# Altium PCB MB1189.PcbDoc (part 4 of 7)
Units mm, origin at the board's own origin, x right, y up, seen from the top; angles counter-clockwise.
Board outline 60.03 x 127.03 mm, 6 copper layers (TOP, L2_GND, L3_VCC, L4_SIG, L5_GND, BOTTOM), stack 1.58 mm thick; 273 components, 264 nets, 1114 pads, 811 vias.
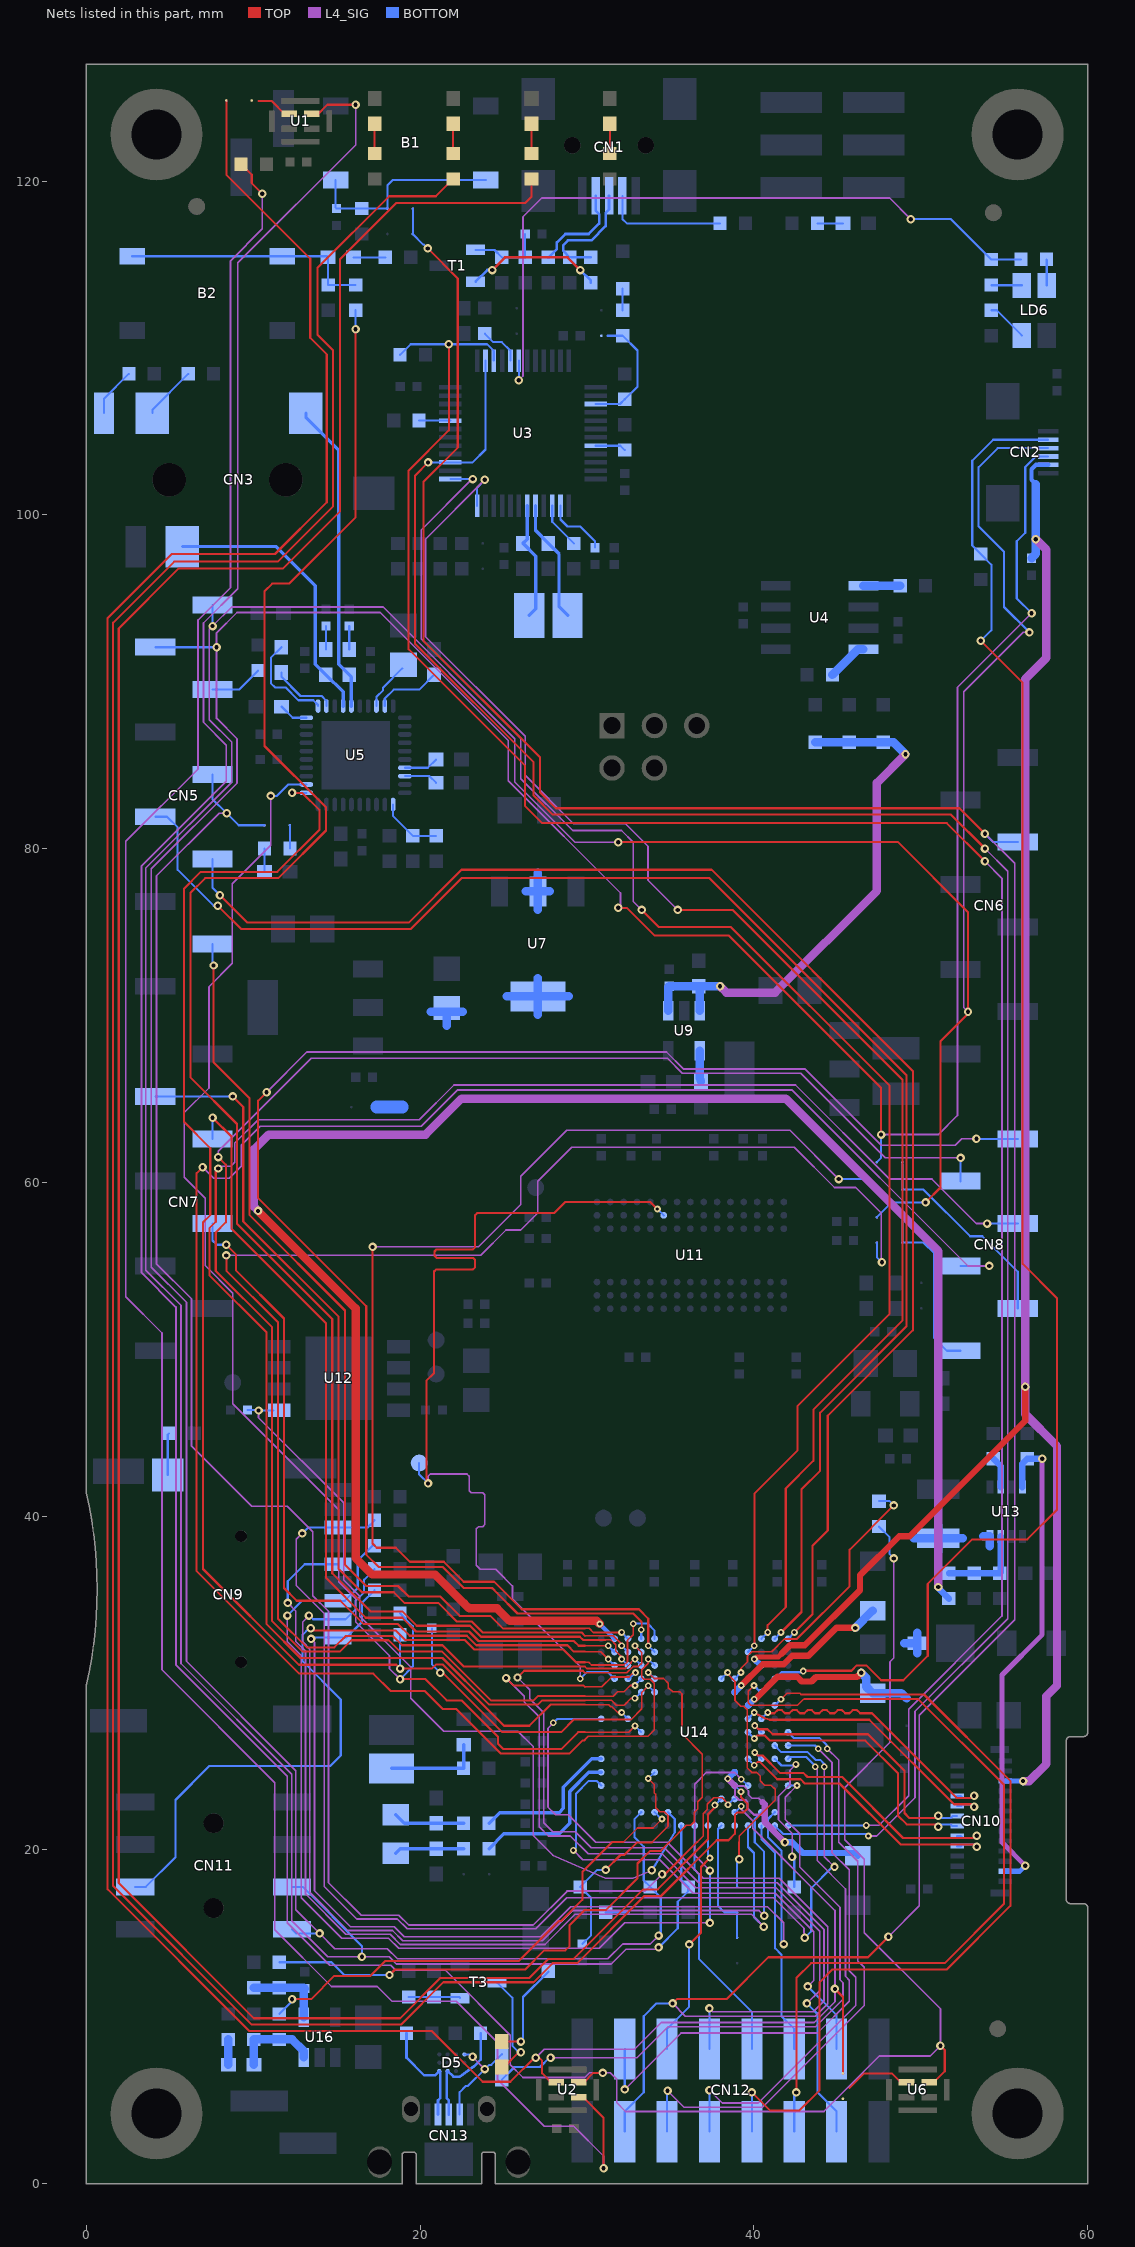
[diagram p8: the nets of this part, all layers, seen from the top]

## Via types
v1: diameter 0.61/0.61/0.61 (per signal layer), hole 0.305, TOP to BOTTOM, 321 vias
v2: diameter 0.508/0.508/0.508 (per signal layer), hole 0.254, TOP to BOTTOM, 247 vias
v3: diameter 0.406/0.406/0.406 (per signal layer), hole 0.203, TOP to BOTTOM, 243 vias

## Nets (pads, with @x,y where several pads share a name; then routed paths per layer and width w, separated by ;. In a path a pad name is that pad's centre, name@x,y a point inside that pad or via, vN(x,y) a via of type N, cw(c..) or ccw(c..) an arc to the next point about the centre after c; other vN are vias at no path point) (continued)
HSSI_CLK_N: CN10.12 U14.H13 | length 16.6
  TOP w0.129: v3(40.056,27.444) 40.271,27.229 40.818,27.229 41.123,26.924 46.838,26.924 49.022,24.74 49.022,22.205 49.32,21.907 50.913,21.907 v2(51.052,22.047)
  BOTTOM w0.13: v3(40.056,27.444) U14.H13@40.449,27.051 ; v2(51.052,22.047) 51.192,21.907 51.794,21.907 51.903,22.017 CN10.12@52.175,22.017
HSSI_CLK_P: CN10.14 U14.H12 | length 16.6
  TOP w0.129: v3(40.03,26.67) 40.208,26.848 40.66,26.848 40.965,26.543 46.68,26.543 48.641,24.582 48.641,22.047 49.162,21.526 50.913,21.526 v2(51.052,21.387)
  BOTTOM w0.13: U14.H12@39.649,27.051 v3(40.03,26.67) ; v2(51.052,21.387) 51.192,21.526 51.794,21.526 51.903,21.417 CN10.14@52.175,21.417
HSSI_D0_N: CN10.8 U14.J13 | length 17.2
  TOP w0.129: v3(40.826,28.228) 40.874,28.18 41.221,28.18 41.413,28.372 41.672,28.372 41.863,28.18 42.122,28.18 42.314,28.372 42.573,28.372 42.764,28.18 43.024,28.18 43.215,28.372 43.474,28.372 43.666,28.18 43.925,28.18 44.116,28.372 44.375,28.372 44.567,28.18 44.826,28.18 45.017,28.372 45.277,28.372 45.468,28.18 45.727,28.18 45.919,28.372 46.178,28.372 46.369,28.18 47.08,28.18 52.153,23.107 53.057,23.107 v2(53.197,23.247)
  BOTTOM w0.13: U14.J13@40.449,27.851 v3(40.826,28.228) ; CN10.8@52.175,23.217 52.411,23.217 52.521,23.107 53.057,23.107 v2(53.197,23.247)
HSSI_D0_P: CN10.10 U14.J12 | length 17.1
  TOP w0.129: v3(40.026,28.228) 40.238,28.096 40.686,27.865 40.945,27.799 46.922,27.799 51.995,22.726 53.057,22.726 v2(53.197,22.586)
  BOTTOM w0.13: U14.J12@39.649,27.851 v3(40.026,28.228) ; CN10.10@52.175,22.617 52.411,22.617 52.521,22.726 53.057,22.726 v2(53.197,22.586)
HSSI_D1_N: CN10.16 U14.F13 | length 17.3
  TOP w0.129: v3(40.056,25.832) 40.234,25.654 40.513,25.654 41.554,24.613 42.957,24.613 43.211,24.359 45.288,24.359 48.94,20.707 53.209,20.707 v2(53.349,20.847)
  BOTTOM w0.13: v3(40.056,25.832) 40.068,25.832 U14.F13@40.449,25.451 ; CN10.16@52.175,20.817 52.411,20.817 52.521,20.707 53.209,20.707 v2(53.349,20.847)
HSSI_D1_P: CN10.18 U14.F12 | length 17.3
  TOP w0.129: v3(40.026,25.074) 40.225,25.273 40.355,25.273 41.396,24.232 42.799,24.232 43.053,23.978 45.13,23.978 48.782,20.326 53.209,20.326 v2(53.349,20.186)
  BOTTOM w0.13: U14.F12@39.649,25.451 v3(40.026,25.074) ; CN10.18@52.175,20.217 52.411,20.217 52.521,20.326 53.209,20.326 v2(53.349,20.186)
I2C1_SCL: CN2.3 CN5.10 CN11.3 R140.2 SB11.1 U14.A7 | length 240.3
  TOP w0.127: v2(31.877,80.391) 48.641,80.391 52.832,76.2 v2(52.832,70.231) 52.832,70.104 51.181,68.453 51.181,59.69 v2(50.292,58.801)
  L4_SIG w0.102: v2(31.877,80.391) 29.279,80.391 25.669,84.001 25.669,86.599 17.78,94.488 8.7,94.488 v2(7.556,93.345) 7.366,93.154 7.366,87.732 8.7,86.398 8.7,83.985 3.556,78.842 3.556,54.737 5.664,52.629 5.664,31.166 12.294,24.536 12.294,15.748 14.453,13.589 v2(16.51,13.589) 18.136,13.589 18.567,13.157 31.445,13.157 32.334,14.046 34.188,14.046 v2(34.29,14.148) ; v2(52.832,70.231) 52.578,70.485 52.578,89.408 56.134,92.964 v2(56.515,92.964)
  BOTTOM w0.127: v2(7.556,93.345) CN5.10@7.556,94.615 ; CN11.3@12.318,17.78 12.954,17.78 16.51,14.224 v2(16.51,13.589) ; v2(34.29,14.148) 35.433,15.291 35.433,16.891 36.068,17.526 R140.2@36.068,17.78 35.649,18.199 U14.A7@35.649,21.451 ; SB11.1@47.371,57.912 48.26,58.801 v2(50.292,58.801) ; v2(56.515,92.964) 54.991,94.488 54.991,97.79 53.467,99.314 53.467,102.87 54.606,104.009 CN2.3@57.635,104.009
I2C1_SDA: CN2.4 CN5.9 CN11.1 R142.2 SB9.1 U14.B4 | length 226.7
  TOP w0.127: v2(31.877,76.454) 32.385,76.454 34.036,74.803 38.481,74.803 47.625,65.659 v2(47.625,62.865)
  L4_SIG w0.102: v2(31.877,76.454) 32.004,76.581 32.004,77.343 25.273,84.074 25.273,86.487 17.602,94.158 9.017,94.158 7.798,92.939 v2(7.798,92.075) 7.798,87.808 9.017,86.589 9.017,83.922 3.886,78.791 3.886,54.915 5.994,52.807 5.994,31.293 12.548,24.74 12.548,16.408 v2(13.97,14.986) 14.884,14.072 18.034,14.072 18.644,13.462 31.242,13.462 32.131,14.351 33.782,14.351 v2(34.29,14.859) ; v2(47.625,62.865) 51.054,62.865 52.197,64.008 52.197,89.662 v2(56.642,94.107)
  BOTTOM w0.127: CN5.9@4.127,92.075 v2(7.798,92.075) ; CN11.1@12.318,15.24 12.572,14.986 v2(13.97,14.986) ; U14.B4@33.249,22.251 32.855,21.857 32.855,20.739 33.401,20.193 33.401,18.161 R142.2@33.782,17.78 34.417,17.145 34.417,14.986 v2(34.29,14.859) ; SB9.1@47.371,61.214 47.625,61.468 v2(47.625,62.865) ; v2(56.642,94.107) 55.753,94.996 55.753,98.425 56.261,98.933 56.261,102.874 56.896,103.509 CN2.4@57.635,103.509
I2C2_SCL: R121.2 U5.2 U14.H4 | length 84.6
  TOP w0.102: 29.87,27.051 32.495,27.051 v3(32.872,27.428)
  TOP w0.127: v2(18.796,30.226) 20.32,30.226 21.59,28.956 22.479,28.956 24.663,26.772 24.663,26.365 24.994,26.035 28.448,26.035 29.464,27.051 29.87,27.051
  L4_SIG w0.102: v2(11.049,83.16) 11.049,80.213 8.738,77.902 8.738,73.127 7.341,71.73 7.341,65.659 5.867,64.186 5.867,60.3 7.112,59.055 7.112,55.016 8.763,53.365 8.763,46.736 15.113,40.386 15.113,36.068 16.129,35.052 16.129,33.655 18.161,31.623 18.161,30.861 v2(18.796,30.226)
  BOTTOM w0.102: v3(32.872,27.428) U14.H4@33.249,27.051
  BOTTOM w0.127: v2(11.049,83.16) 11.405,83.16 12.093,83.848 U5.2@13.179,83.848 ; v2(18.796,30.226) 19.558,30.988 19.558,33.401 R121.2@18.796,34.163
I2C2_SDA: R124.2 U5.1 U14.J3 | length 87.8
  TOP w0.102: 29.87,28.702 31.301,28.702 31.428,28.575 31.496,28.575 31.843,28.228 v3(32.072,28.228)
  TOP w0.127: v2(12.319,83.348) 12.918,83.348 13.97,82.296 13.97,81.153 11.43,78.613 6.858,78.613 5.842,77.597 5.842,63.627 7.417,62.052 7.417,58.039 6.985,57.607 6.985,36.83 12.725,31.09 18.567,31.09 v2(18.796,30.861) 20.701,30.861 20.955,31.115 21.336,31.115 25.019,27.432 26.543,27.432 27.813,28.702 29.87,28.702
  BOTTOM w0.102: v3(32.072,28.228) U14.J3@32.449,27.851
  BOTTOM w0.127: v2(12.319,83.348) U5.1@13.179,83.348 ; v2(18.796,30.861) R124.2@18.796,32.893
I2S3_CK: SB6.1 U14.M10 | length 16
  TOP w0.102: v3(38.426,30.628) 38.426,30.535 38.862,30.099 38.862,28.956 39.217,28.601 39.402,28.601 39.61,28.393 39.61,24.906 39.878,24.638 40.132,24.638 40.141,24.629 40.173,24.629 40.382,24.421 40.382,24.388 40.386,24.384 40.386,24.13 40.64,23.876 41.021,23.876 41.275,23.622 41.275,22.987 39.116,20.828 39.116,20.472
  TOP w0.127: v2(39.116,19.431) 39.116,20.472
  BOTTOM w0.127: U14.M10@38.049,30.251 v3(38.426,30.628) ; SB6.1@38.989,17.78 38.989,19.304 v2(39.116,19.431)
K: CN10.23 R58.2 U13.4 | length 30
  L4_SIG w0.305: v2(56.261,19.05) 54.864,20.447 54.864,30.48 57.277,32.893 v2(57.277,43.434)
  BOTTOM w0.305: CN10.23@55.075,18.717 55.928,18.717 v2(56.261,19.05)
  BOTTOM w0.381: U13.4@56.093,41.734 56.093,43.139 R58.2@56.388,43.434 v2(57.277,43.434)
LCD_BL_CTRL: R119.2 U14.R2 | length 111.7
  TOP w0.508: v2(10.287,58.293) 16.129,52.451 16.129,37.49 17.12,36.5 20.898,36.5 22.63,34.768 22.636,34.768 22.936,34.468 24.613,34.468 25.362,33.718 30.581,33.718 v3(30.764,33.536)
  L4_SIG w0.508: v2(10.287,58.293) 10.033,58.547 10.033,61.976 10.922,62.865 20.32,62.865 22.479,65.024 41.91,65.024 51.054,55.88 v2(51.054,35.75)
  BOTTOM w0.254: v3(30.764,33.536) U14.R2@31.649,32.651
  BOTTOM w0.381: v2(51.054,35.75) 51.054,35.687 R119.2@51.689,35.052
LCD_INT: CN2.2 R36.2 U14.M14 | length 94.9
  TOP w0.102: v3(42.955,30.71) 42.978,30.734 v3@43.028,30.734
  TOP w0.127: v3@43.028,30.734 45.847,30.734 46.164,31.051 46.736,31.051 47.625,30.162 48.959,30.162 50.419,31.623 50.419,35.941 53.086,38.608 56.388,38.608 58.166,40.386 58.166,53.061 56.109,55.118 56.109,89.941 v2(53.594,92.456)
  BOTTOM w0.127: U14.M14@41.249,30.251 41.643,30.645 42.889,30.645 v3(42.955,30.71) ; v2(53.594,92.456) 54.229,93.091 54.229,97.028 R36.2@53.594,97.663 53.086,98.171 53.086,103.251 54.344,104.509 CN2.2@57.635,104.509
LCD_RST: CN2.5 CN10.5 R34.2 U14.N13 | length 110.1
  TOP w0.305: v3(40.03,31.428) 40.17,31.568 41.474,31.568 41.656,31.75
  TOP w0.381: 41.656,31.75 42.164,32.258 43.053,32.258 46.355,35.56 46.355,36.449 48.704,38.798 49.34,38.798 56.261,45.72 v2(56.261,47.752)
  L4_SIG w0.508: v2(56.134,24.117) 56.502,24.117 57.531,25.146 57.531,29.21 58.166,29.845 58.166,44.196 56.261,46.101 v2(56.261,47.752) 56.261,90.17 57.531,91.44 57.531,97.917 v2(56.896,98.552)
  BOTTOM w0.254: 56.896,101.854 56.642,102.108 56.642,102.743 56.908,103.009 CN2.5@57.635,103.009
  BOTTOM w0.305: CN10.5@55.075,24.117 v2(56.134,24.117)
  BOTTOM w0.381: v3(40.03,31.428) 40.408,31.051 U14.N13@40.449,31.051
  BOTTOM w0.508: R34.2@56.642,97.409 56.896,97.663 v2(56.896,98.552) 56.896,101.854
LED_STLINK: R11.1 R17.1 U3.30 | length 42.9
  L4_SIG w0.102: v2(25.912,108.081) 26.162,108.331 26.162,117.881 27.28,118.999 48.133,118.999 v2(49.403,117.729)
  BOTTOM w0.127: v2(25.912,108.081) U3.30@25.912,109.252 ; v2(49.403,117.729) 51.816,117.729 R17.1@54.229,115.316 R11.1@56.007,115.316
MCO: R35.1 U3.29 | length 2.6
  BOTTOM w0.127: R35.1@23.876,110.871 24.384,110.363 24.892,110.363 25.412,109.843 U3.29@25.412,109.252
MIC_CK: R87.1 U1.3 U2.3 U6.3 | length 209.1
  TOP w0.127: U1.3@13.502,123.996 13.849,123.996 14.44,124.587 v2(16.129,124.587) ; U2.3@29.504,6.013 29.762,6.013 30.378,6.629 v2(30.937,6.629) ; U6.3@50.506,6.013 50.717,6.013 51.435,6.731 51.435,8.001 v2(51.181,8.255)
  L4_SIG w0.102: v2(16.129,124.587) 16.129,122.174 9.068,115.113 9.068,95.58 7.01,93.523 7.01,87.579 8.382,86.208 8.382,84.049 3.302,78.969 3.302,54.585 5.359,52.527 5.359,31.09 12.04,24.409 12.04,15.621 14.58,13.081 18.237,13.081 18.542,12.776 21.514,12.776 25.4,8.89 25.4,7.112 26.162,6.35 29.87,6.35 30.15,6.629 v2(30.937,6.629) 31.394,6.629 31.775,6.248 31.775,4.851 32.309,4.318 44.196,4.318 47.522,7.644 50.57,7.644 v2(51.181,8.255) 51.181,10.465 46.609,15.037 46.609,19.431 45.441,20.599 45.441,23.724 48.158,26.441 48.158,31.267 48.387,31.496 v2(48.387,37.465)
  BOTTOM w0.127: R87.1@47.498,39.37 48.133,38.735 48.133,37.719 v2(48.387,37.465)
MICROAB_N: CN13.2 D5.D1 R160.1 | length 6.7
  BOTTOM w0.155: R160.1@19.177,9.017 19.177,7.544 20.244,6.477 20.883,6.477 D5.D1@21.145,6.739 21.201,6.682 21.201,5.122 21.067,4.988 CN13.2@21.067,4.135
MICROAB_P: CN13.3 D5.C1 R159.1 | length 6.8
  BOTTOM w0.155: CN13.3@21.717,4.135 21.717,4.988 21.582,5.122 21.582,6.676 D5.C1@21.645,6.739 21.983,6.401 22.377,6.401 23.228,7.023 23.622,7.417 R159.1@23.622,9.017
NETB1_1: B1.1 B1.4 C3.2 R6.2 SB1.2 | length 12.2
  BOTTOM w0.127: B1.4@14.931,120.078 14.931,118.419 C3.2@14.986,118.364 R6.2@16.51,118.364 SB1.2@18.034,118.364 18.034,119.75 18.363,120.078 B1.1@23.931,120.078
NetB2_2: B2.2 B2.3 C4.2 R18.1 R19.1 | length 15.1
  BOTTOM w0.127: B2.3@2.739,115.506 B2.2@11.739,115.506 14.414,115.506 C4.2@14.478,115.443 R19.1@14.478,113.792 R18.1@16.129,113.792
NETC4_1: C4.1 R10.2 | length 1.9
  BOTTOM w0.127: C4.1@16.002,115.443 R10.2@17.907,115.443
NETC15_1: C15.1 U5.18 | length 2.9
  BOTTOM w0.127: U5.18@17.379,88.548 17.379,89.098 17.78,89.499 17.78,89.662 C15.1@18.923,90.805
NETC18_1: C18.1 U5.11 | length 5.9
  BOTTOM w0.127: C18.1@11.684,92.075 11.049,91.44 11.049,89.916 11.303,89.662 11.938,89.662 12.7,88.9 13.589,88.9 13.879,88.61 U5.11@13.879,88.548
NETC18_2: C18.2 U5.12 | length 3.9
  BOTTOM w0.127: C18.2@11.684,90.551 11.684,90.297 12.827,89.154 14.097,89.154 14.379,88.872 U5.12@14.379,88.548
NETC19_2: C19.2 U5.19 | length 4
  BOTTOM w0.127: U5.19@17.879,88.548 17.879,88.999 18.415,89.535 19.939,89.535 C19.2@20.828,90.424
NETC20_1: C20.1 CN3.6 U5.15 | length 18.7
  BOTTOM w0.203: CN3.6@13.153,106.108 13.153,105.846 15.113,103.886 15.113,91.059 C20.1@15.748,90.424 15.879,90.293 U5.15@15.879,88.548
NETC20_2: C20.2 R39.1 | length 1.4
  BOTTOM w0.127: C20.2@15.748,91.948 R39.1@15.748,93.345
NETC21_1: C21.1 CN3.4 U5.14 | length 16.8
  BOTTOM w0.203: CN3.4@5.753,98.108 11.366,98.108 13.716,95.758 13.716,91.059 C21.1@14.351,90.424 15.379,89.396 U5.14@15.379,88.548
NETC21_2: C21.2 R40.1 | length 1.4
  BOTTOM w0.127: C21.2@14.351,91.948 R40.1@14.351,93.345
NETC22_2: C22.2 U5.10 | length 1.8
  BOTTOM w0.127: C22.2@11.684,88.519 12.355,87.848 U5.10@13.179,87.848
NETC24_2: C24.2 U5.27 | length 2.1
  BOTTOM w0.127: U5.27@19.079,84.848 20.459,84.848 C24.2@20.955,85.344
NETC27_2: C27.2 U5.28 | length 2
  BOTTOM w0.127: U5.28@19.079,84.348 20.554,84.348 C27.2@20.955,83.947
NETC33_2: C33.2 C34.2 D2.2 D3.2 D4.2 U9.1 U9.3 | length 32.7
  L4_SIG w0.508: v2(37.973,71.755) 38.354,71.374 41.275,71.374 47.371,77.47 47.371,83.947 v2(49.085,85.661)
  BOTTOM w0.508: U9.1@34.864,70.288 34.864,71.694 C34.2@34.925,71.755 C33.2@36.703,71.755 ; U9.3@36.764,70.288 36.764,71.694 C33.2@36.703,71.755 ; v2(37.973,71.755) C33.2@36.703,71.755 ; D4.2@43.688,86.378 D3.2@45.72,86.378 D2.2@47.752,86.378 48.369,86.378 v2(49.085,85.661)
NETC37_1: C37.1 SB8.1 U7.2 U7.4 | length 13.8
  BOTTOM w0.508: 20.624,70.231 C37.1@21.59,70.231 ; 21.59,69.392 C37.1@21.59,70.231 ; 22.556,70.231 C37.1@21.59,70.231 ; 25.196,71.145 U7.4@27.051,71.145 ; 26.339,77.445 U7.2@27.051,77.445 ; 27.051,70.039 U7.4@27.051,71.145 ; 27.051,72.25 U7.4@27.051,71.145 ; 27.051,76.34 U7.2@27.051,77.445 ; 27.051,78.551 U7.2@27.051,77.445 ; 27.763,77.445 U7.2@27.051,77.445 ; 28.906,71.145 U7.4@27.051,71.145
  BOTTOM w0.762: SB8.1@17.399,64.516 18.923,64.516
NETC39_2: C39.2 U9.4 | length 1.9
  BOTTOM w0.508: U9.4@36.764,67.888 36.764,66.233 C39.2@36.83,66.04
NETC76_1: C76.1 U14.L11 | length 10.3
  TOP w0.381: v3(39.243,29.845) 40.521,31.123 41.791,31.123 42.291,31.623 43.276,31.623 44.952,33.299 v2(46.076,33.299)
  BOTTOM w0.381: U14.L11@38.849,29.451 v3(39.243,29.845)
  BOTTOM w0.508: v2(46.076,33.299) C76.1@47.117,34.341
NETC81_1: C81.1 SB14.2 U14.K12 | length 11.5
  TOP w0.381: v3(40.026,29.028) 40.077,29.028 41.416,30.367 42.598,30.367 42.878,30.086 43.452,30.086 43.719,30.353 46.177,30.353 v2(46.431,30.607)
  BOTTOM w0.381: U14.K12@39.649,28.651 v3(40.026,29.028)
  BOTTOM w0.508: v2(46.431,30.607) 46.736,30.302 46.736,29.769 C81.1@47.117,29.388 48.844,29.388 49.149,29.083
NETC85_1: C85.1 R131.2 X2.2 | length 5.7
  BOTTOM w0.203: X2.2@18.288,24.885 18.295,24.892 R131.2@22.606,24.892 C85.1@22.606,26.289
NETC93_1: C93.1 R132.1 X3.1 | length 4.2
  BOTTOM w0.203: X3.1@18.542,19.805 18.803,20.066 C93.1@20.955,20.066 R132.1@22.606,20.066
NETC94_1: C94.1 R133.1 X3.2 | length 4.3
  BOTTOM w0.203: X3.2@18.542,22.105 19.057,21.59 C94.1@20.955,21.59 R133.1@22.606,21.59
NETC96_1: C96.1 U14.E11 | length 14.1
  L4_SIG w0.102: 38.858,23.83 39.374,23.83 39.675,23.528 39.675,23.294 39.883,23.086 40.287,23.086 40.513,22.86
  L4_SIG w0.127: 38.858,23.83 38.858,23.245 39.116,22.987 39.497,22.987 39.624,22.86 39.624,22.479 40.005,22.098 40.64,22.098
  L4_SIG w0.381: v3(38.43,24.257) 38.858,23.83 ; 40.513,22.86 40.64,22.733 40.64,22.098 40.64,21.666 v2(41.859,20.447)
  BOTTOM w0.381: v3(38.43,24.257) 38.824,24.651 U14.E11@38.849,24.651 ; v2(41.859,20.447) 42.291,20.447 42.931,19.807 46.055,19.807 C96.1@46.228,19.634
NETCN1_2: CN1.2 R14.1 | length 5.8
  BOTTOM w0.155: R14.1@27.686,115.443 28.194,115.951 28.194,116.335 28.699,116.84 30.096,116.84 30.728,117.472 30.728,118.027 30.518,118.237 CN1.2@30.518,119.126
NETCN1_3: CN1.3 R12.1 R13.1 | length 7.1
  BOTTOM w0.155: R12.1@30.226,115.443 R13.1@28.956,115.443 28.575,115.824 28.575,116.177 28.857,116.459 30.254,116.459 31.109,117.314 31.109,118.11 31.318,118.319 CN1.3@31.318,119.126
NETCN1_4: CN1.4 R8.1 | length 7.3
  BOTTOM w0.127: CN1.4@32.118,119.126 32.118,117.742 32.385,117.475 R8.1@37.973,117.475
NETCN3_2: CN3.2 R24.1 | length 3
  BOTTOM w0.127: CN3.2@1.053,106.108 1.053,106.971 R24.1@2.54,108.458
NETCN3_3: CN3.3 R23.1 | length 3.2
  BOTTOM w0.127: CN3.3@3.953,106.108 3.953,106.315 R23.1@6.096,108.458
NETCN5_8: CN5.8 R41.2 | length 3.2
  BOTTOM w0.127: CN5.8@7.556,89.535 9.144,89.535 R41.2@10.287,90.678
NETCN8_5: CN8.5 SB9.2 SB10.2 | length 12.7
  BOTTOM w0.127: 48.895,61.087 SB10.2@48.895,59.563 50.165,59.563 52.959,56.769 53.696,56.769 55.816,54.648 CN8.5@55.816,52.451
NETCN8_6: CN8.6 SB11.2 SB12.2 | length 10.7
  BOTTOM w0.127: SB11.2@48.895,57.912 SB12.2@48.895,56.388 50.165,56.388 50.8,55.753 50.8,50.673 51.562,49.911 CN8.6@52.387,49.911
NETCN9_10: CN9.10 R57.2 | length 2.5
  BOTTOM w0.127: CN9.10@4.871,42.467 4.871,44.876 R57.2@4.953,44.958
NETCN13_4: CN13.4 D5.A3 R161.1 | length 6.4
  L4_SIG w0.102: v2(23.139,7.595) v2(23.876,6.858)
  BOTTOM w0.127: CN13.4@22.367,4.135 22.367,5.476 22.733,5.842 22.86,5.842 v2(23.876,6.858) 24.13,7.112 24.257,7.112 R161.1@24.892,7.747 ; D5.A3@22.645,7.739 22.995,7.739 v2(23.139,7.595)
NETD1_2: D1.2 R22.1 | length 1.3
  BOTTOM w0.127: R22.1@32.131,112.268 D1.2@32.131,113.556
NETL4_2: L4.2 U13.8 Z1.1 | length 7.5
  BOTTOM w0.508: 49.009,32.385 Z1.1@49.784,32.385 ; 49.58,38.659 L4.2@51.054,38.659 ; 49.784,31.775 Z1.1@49.784,32.385 ; 49.784,32.995 Z1.1@49.784,32.385 ; 51.054,37.871 L4.2@51.054,38.659 ; 51.054,39.447 L4.2@51.054,38.659 ; 52.528,38.659 L4.2@51.054,38.659 ; 53.736,38.784 U13.8@54.143,38.784 54.143,38.187
NETLD1_2: LD1.2 R2.2 | length 1.8
  TOP w0.127: R2.2@17.272,121.666 LD1.2@17.272,123.444
NETLD2_2: LD2.2 R3.2 | length 1.8
  TOP w0.127: R3.2@21.971,121.666 LD2.2@21.971,123.444
NETLD3_2: LD3.2 R4.2 | length 1.8
  TOP w0.127: R4.2@26.67,121.666 LD3.2@26.67,123.444
NETLD4_2: LD4.2 R5.2 | length 1.8
  TOP w0.127: R5.2@31.369,121.666 LD4.2@31.369,123.444
NETLD5_1: LD5.1 R7.1 | length 1.5
  BOTTOM w0.127: R7.1@43.815,117.475 LD5.1@45.339,117.475
NETLD6_2: LD6.2 R11.2 | length 1.6
  BOTTOM w0.127: R11.2@57.531,115.316 57.555,115.292 LD6.2@57.555,113.767
NETLD6_3: LD6.3 R17.2 | length 1.8
  BOTTOM w0.127: R17.2@54.229,113.792 54.254,113.767 LD6.3@56.054,113.767
NETLD6_4: LD6.4 R21.1 | length 2.4
  BOTTOM w0.127: R21.1@54.229,112.268 54.553,112.268 LD6.4@56.054,110.767
NETLD7_1: LD7.1 R49.2 | length 1.4
  BOTTOM w0.127: LD7.1@10.668,78.613 R49.2@10.668,80.01
NETLD8_1: LD8.1 R153.1 | length 6
  TOP w0.127: LD8.1@24.892,8.509 v2(26.035,8.509)
  BOTTOM w0.127: v2(26.035,8.509) 26.162,8.636 26.162,11.176 R153.1@27.686,12.7
NETLD8_2: LD8.2 T3.3 | length 6.4
  TOP w0.127: LD8.2@24.892,6.985 25.019,6.985 25.908,7.874 v2(26.035,7.874)
  BOTTOM w0.127: T3.3@24.595,12.065 25.527,11.133 25.527,8.255 25.908,7.874 v2(26.035,7.874)
NETLD9_1: LD9.1 R158.1 | length 1.5
  BOTTOM w0.508: LD9.1@8.509,7.112 R158.1@8.509,8.636
NETLD9_2: LD9.2 R156.2 R157.2 U16.3 | length 5.2
  BOTTOM w0.508: LD9.2@10.033,7.112 R157.2@10.033,8.636 R156.2@11.557,8.636 12.319,8.636 13.02,7.935 U16.3@13.02,7.563
NETR1_1: R1.1 U2.2 | length 145.8
  TOP w0.127: R1.1@9.271,121.031 9.906,120.396 9.906,119.888 v2(10.541,119.253) ; U2.2@29.504,5.163 29.762,5.163 30.988,3.937 v2(30.988,0.914)
  L4_SIG w0.102: v2(10.541,119.253) 10.541,117.145 8.636,115.24 8.636,95.656 6.68,93.701 6.68,84.76 2.362,80.442 2.362,53.137 4.521,50.978 4.521,30.785 11.278,24.028 11.278,15.215 14.681,11.811 17.424,11.811 18.313,10.922 22.156,10.922 24.638,8.44 24.638,6.223 27.432,3.429 29.21,3.429 30.988,1.651 v2(30.988,0.914)
NETR9_1: R9.1 R15.1 R16.2 T1.1 | length 4.5
  BOTTOM w0.127: T1.1@23.325,115.885 24.45,115.885 R16.2@24.892,115.443 R15.1@26.289,115.443 R9.1@26.289,116.84
NETR12_2: R12.2 T1.2 | length 8.2
  TOP w0.155: v2(24.32,114.681) 25.082,115.443 28.829,115.443 v2(29.591,114.681)
  BOTTOM w0.155: T1.2@23.325,113.985 24.021,114.681 v2(24.32,114.681) ; v2(29.591,114.681) 30.226,114.046 R12.2@30.226,113.919
NETR22_2: R22.2 R25.1 SB16.2 U3.39 | length 7.2
  BOTTOM w0.127: U3.39@30.512,106.652 31.976,106.652 R25.1@32.258,106.934 33.02,107.696 33.02,109.855 R22.2@32.131,110.744 31.242,110.744
NETR26_2: R26.2 U3.20 | length 1.9
  BOTTOM w0.127: R26.2@19.939,105.664 19.951,105.652 U3.20@21.812,105.652
NETR27_2: R27.2 U3.44 | length 1.9
  BOTTOM w0.127: U3.44@30.512,104.152 31.992,104.152 R27.2@32.258,103.886
NETR28_2: R28.2 U3.2 | length 3.8
  BOTTOM w0.127: U3.2@28.412,100.552 28.412,99.731 28.829,99.314 29.591,99.314 30.48,98.425 R28.2@30.48,98.044
NETR29_2: R29.2 U3.3 | length 2.8
  BOTTOM w0.127: U3.3@27.912,100.552 27.912,99.596 R29.2@29.21,98.298
NETR37_1: R37.1 U4.5 | length 2.2
  BOTTOM w0.508: U4.5@46.566,95.758 R37.1@48.768,95.758
NETR42_2: R42.2 U4.8 | length 2.5
  BOTTOM w0.508: R42.2@44.704,90.424 46.228,91.948 U4.8@46.566,91.948
NETR43_2: R43.2 R151.1 R152.2 U16.4 | length 4.8
  BOTTOM w0.508: R43.2@10.033,11.735 R151.1@11.557,11.735 13.03,11.735 R152.2@13.081,11.684 13.02,11.623 U16.4@13.02,9.963
NETR46_1: R46.1 R47.1 U5.31 | length 3.8
  BOTTOM w0.127: U5.31@18.379,82.648 18.379,81.951 R47.1@19.558,80.772 R46.1@20.955,80.772
NETR49_1: R49.1 SB5.1 | length 1.4
  BOTTOM w0.127: R49.1@12.192,80.01 SB5.1@12.192,81.407
NETR59_1: R59.1 U13.2 | length 1.9
  BOTTOM w0.381: R59.1@54.356,43.434 54.793,42.997 U13.2@54.793,41.734
NETR117_1: R117.1 R118.1 R119.1 U13.7 | length 5.3
  BOTTOM w0.381: R119.1@51.689,36.576 R118.1@53.213,36.576 R117.1@54.737,36.576 54.793,36.632 U13.7@54.793,38.784
NETR122_2: R122.2 U14.L5 | length 19.1
  TOP w0.102: 29.87,27.813 32.639,27.813 33.274,28.448 33.274,29.43 v3(33.672,29.828)
  TOP w0.127: v2(21.209,30.607) 21.361,30.607 24.917,27.051 28.448,27.051 29.21,27.813 29.87,27.813
  BOTTOM w0.127: R122.2@20.701,33.274 20.701,31.115 v2(21.209,30.607) ; v3(33.672,29.828) U14.L5@34.049,29.451
NETR143_2: R143.2 SB15.2 | length 1.4
  BOTTOM w0.127: R143.2@31.115,16.256 SB15.2@32.512,16.256
NETR144_1: R144.1 R149.1 U14.E5 | length 14.7
  TOP w0.102: v3(33.672,24.274) 34.036,23.91 34.036,23.407 34.116,23.327 34.116,22.526 34.354,22.289 34.632,22.289 34.849,22.073 34.849,21.412 33.909,20.472
  TOP w0.127: v2(31.115,18.796) 32.004,19.685 32.236,19.685 32.998,20.447 33.884,20.447 33.909,20.472
  BOTTOM w0.102: v3(33.672,24.274) U14.E5@34.049,24.651
  BOTTOM w0.127: R149.1@29.718,14.351 30.226,14.859 30.226,17.145 R144.1@29.591,17.78 30.607,18.796 v2(31.115,18.796)
NETR154_2: R154.2 R155.2 T3.1 | length 3.1
  BOTTOM w0.127: R155.2@19.304,11.176 R154.2@20.828,11.176 22.334,11.176 T3.1@22.395,11.115
NETSB17_1: SB17.1 U1.4 | length 2.2
  TOP w0.127: 10.312,124.816 10.414,124.816 11.1,124.816 11.919,123.996 U1.4@12.152,123.996
NETSB18_1: SB18.1 U6.4 | length 4
  TOP w0.127: 45.72,5.715 46.609,6.604 48.26,6.604 48.851,6.013 U6.4@49.156,6.013
NRST: CN6.3 CN12.4 SB1.1 SB2.2 U14.J1 | length 206.2
  TOP w0.127: v2(20.447,115.976) 22.25,114.173 22.25,104.038 20.193,101.981 20.193,92.456 27.178,85.471 27.178,83.378 28.133,82.423 52.324,82.423 v2(53.848,80.899) ; v2(35.128,10.795) 35.382,11.049 38.354,11.049 40.869,13.564 46.838,13.564 v2(48.063,14.789)
  L4_SIG w0.102: v3(27.976,27.61) 27.661,27.294 27.661,22.555 28.118,22.098 28.88,22.098 30.531,20.447 34.798,20.447 36.957,18.288 41.529,18.288 44.425,15.392 44.425,10.782 43.676,10.033 35.89,10.033 v2(35.128,10.795) ; v2(48.063,14.789) 49.911,16.637 49.911,28.067 55.626,33.782 55.626,79.121 v2(53.848,80.899)
  BOTTOM w0.127: SB1.1@19.558,118.364 SB2.2@19.558,116.84 20.193,116.205 20.218,116.205 v2(20.447,115.976) ; v3(27.976,27.61) 27.991,27.61 28.232,27.851 U14.J1@30.849,27.851 ; CN12.4@32.258,3.113 32.258,4.318 33.401,5.461 33.401,10.033 34.163,10.795 v2(35.128,10.795) ; v2(53.848,80.899) 54.356,80.391 CN6.3@55.816,80.391
OSC_IN: C10.1 U3.5 X1.1 | length 7.4
  BOTTOM w0.203: U3.5@26.912,100.552 26.912,99.072 C10.1@27.686,98.298 28.321,97.663 28.321,94.495 X1.1@28.836,93.98
OSC_OUT: C11.1 U3.6 X1.2 | length 7.2
  BOTTOM w0.203: U3.6@26.412,100.552 26.412,98.548 C11.1@26.162,98.298 26.924,97.536 26.924,94.368 X1.2@26.536,93.98
PA0: R18.2 U14.N3 | length 109.8
  TOP w0.102: 29.87,32.571 29.976,32.571 31.111,32.571 31.124,32.584 31.419,32.584 31.432,32.571 31.437,32.571 31.716,32.292 31.716,31.911 32.072,31.555 v3(32.072,31.428)
  TOP w0.127: v2(16.129,111.125) 16.129,99.873 12.141,95.885 11.125,95.885 10.668,95.428 10.668,86.157 14.351,82.474 14.351,81.092 11.491,78.232 7.112,78.232 6.223,77.343 6.223,66.294 9.017,63.5 9.017,57.531 14.732,51.816 14.732,36.576 17.018,34.29 18.923,34.29 19.787,33.426 22.983,33.426 23.644,32.766 29.57,32.766 29.765,32.571 29.87,32.571
  BOTTOM w0.127: v2(16.129,111.125) R18.2@16.129,112.268 ; v3(32.072,31.428) U14.N3@32.449,31.051
PA1: CN7.4 U14.N2 | length 45.7
  TOP w0.102: 29.87,31.877 30.823,31.877 v3(31.272,31.428)
  TOP w0.127: v2(8.382,56.261) 8.954,55.689 8.954,54.724 11.836,51.841 11.836,35.687 12.598,34.925 15.215,34.925 16.612,33.528 18.669,33.528 19.367,32.829 22.796,32.829 23.368,32.258 28.829,32.258 29.21,31.877 29.87,31.877
  BOTTOM w0.127: CN7.4@7.556,57.531 7.556,56.515 7.81,56.261 v2(8.382,56.261) ; v3(31.272,31.428) U14.N2@31.649,31.051
PA2: CN7.6 U14.P2 | length 50.8
  TOP w0.102: 29.87,32.228 v3(31.272,32.228)
  TOP w0.127: v2(7.556,63.881) 8.687,62.751 8.687,57.226 14.351,51.562 14.351,36.297 16.739,33.909 18.923,33.909 19.748,33.084 22.924,33.084 23.495,32.512 29.21,32.512 29.494,32.228 29.87,32.228
  BOTTOM w0.127: CN7.6@7.556,62.611 v2(7.556,63.881) ; v3(31.272,32.228) U14.P2@31.649,31.851
PA4: SB12.1 U14.N4 | length 96
  TOP w0.102: 29.87,30.988 29.997,30.861 32.258,30.861 32.266,30.869 32.303,30.869 32.631,31.197 32.631,31.234 32.825,31.428 v3(32.872,31.428)
  TOP w0.127: v2(8.382,55.626) 8.382,54.712 11.481,51.613 11.481,33.858 13.208,32.131 14.859,32.131 15.545,32.817 18.364,32.817 18.923,32.258 21.336,32.258 22.606,30.988 29.87,30.988
  L4_SIG w0.102: v2(8.382,55.626) 23.622,55.626 25.146,57.15 26.035,57.15 27.051,58.166 27.051,60.071 29.083,62.103 42.418,62.103 44.831,59.69 46.101,59.69 47.625,58.166 47.625,55.27 v2(47.676,55.22)
  BOTTOM w0.127: v3(32.872,31.428) U14.N4@33.249,31.051 ; SB12.1@47.371,56.388 47.371,55.524 v2(47.676,55.22)
PA5: CN12.7 U14.P4 | length 52.4
  TOP w0.102: 29.87,30.607 32.384,30.607 32.756,30.979 32.766,30.988 33.071,30.988 33.274,31.191 33.274,31.826 v3(32.872,32.228)
  TOP w0.127: v2(25.832,30.328) 26.238,30.734 29.743,30.734 29.87,30.607
  L4_SIG w0.102: v2(25.832,30.328) 26.568,29.591 26.568,29.058 27.407,28.219 27.407,21.615 27.94,21.082 29.286,21.082 30.251,20.117 34.62,20.117 36.703,18.034 41.402,18.034 44.196,15.24 44.196,10.922 43.561,10.287 37.541,10.287 v2(37.338,10.49)
  BOTTOM w0.102: v3(32.872,32.228) U14.P4@33.249,31.851
  BOTTOM w0.127: CN12.7@37.338,8.063 v2(37.338,10.49)
PA6: CN7.7 U14.P3 | length 55
  TOP w0.102: 29.87,32.825 31.564,32.825 32.072,32.317 v3(32.072,32.228)
  TOP w0.127: v2(8.763,65.151) 9.398,64.516 9.398,57.658 15.113,51.943 15.113,36.83 16.51,35.433 18.415,35.433 19.05,34.798 21.082,34.798 22.2,33.68 23.089,33.68 23.749,33.02 29.675,33.02 29.87,32.825
  BOTTOM w0.127: CN7.7@4.127,65.151 v2(8.763,65.151) ; v3(32.072,32.228) U14.P3@32.449,31.851
PA7: CN5.2 U14.R3 | length 59.3
  TOP w0.102: 29.87,33.274 30.124,33.274 30.37,33.028 v3(32.072,33.028)
  TOP w0.127: v2(7.62,73) 7.62,67.183 9.779,65.024 9.779,58.039 15.494,52.324 15.494,37.084 16.764,35.814 18.669,35.814 19.304,35.179 21.209,35.179 22.365,34.023 24.208,34.023 24.958,33.274 29.87,33.274
  BOTTOM w0.127: CN5.2@7.556,74.295 7.556,73.063 v2(7.62,73) ; v3(32.072,33.028) U14.R3@32.449,32.651
PA8: CN12.3 U14.F15 | length 34.9
  L4_SIG w0.102: v2(32.258,5.639) 35.636,9.017 43.815,9.017 45.72,10.922 45.72,12.192 45.491,12.421 45.491,17.653 43.79,19.355 43.79,24.875 v3(43.683,24.982)
  BOTTOM w0.127: v2(32.258,5.639) CN12.3@32.258,8.063 ; U14.F15@42.049,25.451 42.15,25.552 43.155,25.552 43.663,25.044 43.663,25.002 v3(43.683,24.982)
PA10: R161.2 U14.D15 | length 37.5
  L4_SIG w0.102: v2(27.813,7.544) 32.995,7.544 34.849,9.398 43.688,9.398 45.339,11.049 45.339,12.04 45.161,12.217 45.161,16.561 42.748,18.974 42.748,20.955 41.885,21.819 41.885,23.153 v3(42.582,23.851)
  BOTTOM w0.102: U14.D15@42.049,23.851 v3(42.582,23.851)
  BOTTOM w0.127: R161.2@24.892,6.223 25.654,6.985 27.178,6.985 27.737,7.544 v2(27.813,7.544)
PA13: R20.2 U3.27 U14.A15 | length 133.8
  TOP w0.127: v2(21.717,110.236) 21.717,105.08 19.304,102.667 19.304,91.948 26.289,84.963 26.289,82.55 27.305,81.534 51.562,81.534 v2(53.848,79.248)
  L4_SIG w0.102: v3(46.736,21.463) 47.498,21.463 49.276,23.241 49.276,28.423 54.864,34.011 54.864,78.232 v2(53.848,79.248)
  BOTTOM w0.127: R20.2@18.796,109.601 19.431,110.236 v2(21.717,110.236) 24.01,110.236 24.412,109.834 U3.27@24.412,109.252 ; U14.A15@42.049,21.451 46.724,21.451 v3(46.736,21.463)
PA14: U3.15 U3.26 U14.A14 | length 130.1
  TOP w0.127: v2(20.475,103.152) 19.685,102.362 19.685,92.286 26.797,85.174 26.797,83.185 27.94,82.042 51.816,82.042 v2(53.848,80.01)
  L4_SIG w0.102: v3(46.863,20.828) 47.371,20.828 49.657,23.114 49.657,28.296 55.22,33.858 55.22,78.638 v2(53.848,80.01)
  BOTTOM w0.127: v2(20.475,103.152) U3.15@21.812,103.152 23.142,103.152 23.912,103.922 U3.26@23.912,109.252 ; U14.A14@41.249,21.451 41.745,20.955 46.736,20.955 v3(46.863,20.828)
PA15: CN12.11 U14.A13 | length 14.2
  BOTTOM w0.127: U14.A13@40.449,21.451 40.449,20.638 41.275,19.812 41.275,14.097 41.656,13.716 41.656,10.033 42.418,9.271 CN12.11@42.418,8.063
PB0: CN11.4 U14.R5 | length 50.8
  TOP w0.102: 29.87,31.242 30.099,31.242 30.268,31.073 32.219,31.073 32.427,31.281 32.427,32.554 32.765,32.892 v3(32.765,33.551)
  TOP w0.127: v2(13.437,33.274) 13.564,33.147 18.542,33.147 19.113,32.575 22.669,32.575 23.241,32.004 28.575,32.004 29.337,31.242 29.87,31.242
  BOTTOM w0.127: CN11.4@2.922,17.78 3.556,17.78 5.334,19.558 5.334,22.987 7.366,25.019 14.605,25.019 15.24,25.654 15.24,29.007 12.954,31.293 12.954,32.893 13.335,33.274 v2(13.437,33.274) ; v3(32.765,33.551) 32.777,33.564 33.619,33.564 34.049,33.134 U14.R5@34.049,32.651
PB1: CN8.1 U14.R4 | length 98.3
  TOP w0.102: v3(33.249,33.195) 33.249,33.282 33.274,33.307 33.274,33.63
  TOP w0.127: v2(10.795,65.405) 10.287,64.897 10.287,59.055 16.764,52.578 16.764,37.694 17.501,36.957 21.336,36.957 22.606,35.687 24.308,35.687 24.32,35.674 24.335,35.674 24.625,35.384 24.625,35.369 25.832,34.163 32.766,34.163 33.274,33.655 33.274,33.63
  L4_SIG w0.102: v2(10.795,65.405) 13.208,67.818 34.76,67.818 35.776,66.802 43.053,66.802 47.625,62.23 52.07,62.23 52.451,62.611 v2(53.34,62.611)
  BOTTOM w0.127: U14.R4@33.249,32.651 v3(33.249,33.195) ; v2(53.34,62.611) CN8.1@55.816,62.611
PB2: R151.2 U14.M5 | length 41.9
  TOP w0.102: v3(33.672,30.628) 34.036,30.264 34.582,30.264 34.874,29.972 34.874,29.718 35.128,29.464 35.56,29.464 35.687,29.337 35.687,26.949 36.906,25.73 36.906,23.157 36.631,22.881 36.631,22.442 36.427,22.239 36.427,21.675 36.215,21.463 35.941,21.463 34.95,20.472
  TOP w0.127: v2(18.161,12.497) 18.491,12.827 26.289,12.827 27.432,13.97 28.702,13.97 28.956,14.224 28.956,15.494 29.845,16.383 31.115,16.383 33.02,18.288 33.02,19.177 33.782,19.939 34.417,19.939 34.95,20.472
  BOTTOM w0.127: R151.2@11.557,13.259 14.681,13.259 15.443,12.497 v2(18.161,12.497) ; v3(33.672,30.628) U14.M5@34.049,30.251
PB3: SB6.2 SB7.2 U14.A10 | length 7.7
  BOTTOM w0.127: U14.A10@38.049,21.451 37.846,21.248 37.846,16.637 38.227,16.256 SB6.2@38.989,16.256 SB7.2@38.989,14.732
PB4: CN12.5 U14.A9 | length 14.5
  TOP w0.127: v2(36.119,14.326) 36.83,15.037 36.83,18.974 v3(37.363,19.507)
  BOTTOM w0.127: CN12.5@34.798,8.063 34.798,9.271 36.119,10.592 v2(36.119,14.326) ; U14.A9@37.249,21.451 37.249,19.621 v3(37.363,19.507)
PB5: CN12.9 U14.A8 | length 14.8
  BOTTOM w0.127: U14.A8@36.449,21.451 36.449,18.796 36.703,18.542 36.703,13.462 39.878,10.287 CN12.9@39.878,8.063
PB6: R55.1 U12.1 U14.B6 | length 48.5
  L4_SIG w0.102: v2(10.312,46.329) 10.312,45.898 15.418,40.792 15.418,36.17 16.383,35.204 16.383,34.006 19.431,30.958 19.431,29.083 21.412,27.102 25.857,27.102 26.772,26.187 26.772,20.853 27.94,19.685 31.115,18.288 32.766,18.288 v2(33.884,18.771)
  BOTTOM w0.127: R55.1@9.652,46.355 10.286,46.355 v2(10.312,46.329) U12.1@11.213,46.329 ; v2(33.884,18.771) 34.908,20.472 35.255,21.048 35.255,21.845 U14.B6@34.849,22.251
PB7: R156.1 U14.B5 | length 29.4
  TOP w0.102: 31.521,20.472 32.182,20.472 33.02,21.311 33.957,21.311 v3(34.492,21.846)
  TOP w0.127: v2(12.319,11.049) 13.462,11.049 14.859,12.446 17.018,12.446 17.907,13.335 25.908,13.335 28.308,15.735 28.457,15.735 29.718,16.996 29.718,18.669 31.521,20.472
  BOTTOM w0.127: R156.1@11.557,10.16 12.319,10.922 v2(12.319,11.049) ; U14.B5@34.049,22.251 34.454,21.846 v3(34.492,21.846)
PB10: U3.13 U14.P12 | length 92.3
  TOP w0.127: v2(33.274,76.327) 34.29,75.311 38.608,75.311 48.133,65.786 48.133,52.121 42.621,46.609 42.621,43.942 40.026,41.347 v3(40.026,32.228)
  L4_SIG w0.102: v2(23.153,102.152) 23.109,102.108 23.07,102.108 20.066,99.104 20.066,92.583 26.035,86.614 26.035,84.201 29.146,81.09 32.067,81.09 32.766,80.391 32.766,76.835 v2(33.274,76.327)
  BOTTOM w0.127: U3.13@21.812,102.152 v2(23.153,102.152) ; U14.P12@39.649,31.851 v3(40.026,32.228)
PB11: U3.12 U14.R13 | length 91.8
  TOP w0.127: v2(35.433,76.327) 38.735,76.327 48.895,66.167 48.895,51.714 43.561,46.38 43.561,43.307 41.91,41.656 41.91,34.544 40.826,33.46 v3(40.826,33.028)
  L4_SIG w0.102: v2(23.876,102.108) 20.32,98.552 20.32,92.71 26.289,86.741 26.289,84.397 29.181,81.505 32.287,81.505 33.655,80.137 33.655,78.105 v2(35.433,76.327)
  BOTTOM w0.127: U3.12@23.412,100.552 23.412,101.644 v2(23.876,102.108) ; U14.R13@40.449,32.651 v3(40.826,33.028)
PB12: CN12.12 U14.L13 | length 50.1
  TOP w0.102: v3(40.005,29.845) 39.67,29.51 39.67,28.808 39.806,28.673 42.617,28.673 42.977,29.032 43.028,29.032
  TOP w0.127: v2(42.545,5.461) 42.545,12.319 43.434,13.208 51.435,13.208 54.991,16.764 54.991,23.901 49.86,29.032 43.028,29.032
  BOTTOM w0.127: v3(40.005,29.845) 40.399,29.451 U14.L13@40.449,29.451 ; CN12.12@42.418,3.113 42.418,5.334 v2(42.545,5.461)
PB13: CN12.10 U14.K14 | length 51.3
  TOP w0.102: v3(41.626,29.028) 41.984,29.386 42.752,29.386 42.826,29.312 43.028,29.312
  TOP w0.127: v2(39.878,5.461) 40.957,4.381 42.735,4.381 43.942,5.588 43.942,12.065 44.704,12.827 51.562,12.827 55.372,16.637 55.372,24.13 50.19,29.312 43.028,29.312
  BOTTOM w0.127: CN12.10@39.878,3.113 v2(39.878,5.461) ; U14.K14@41.249,28.651 v3(41.626,29.028)
PB14: CN5.5 U14.R14 | length 92.5
  TOP w0.127: v2(7.874,76.581) 9.271,75.184 19.431,75.184 22.479,78.232 37.338,78.232 49.149,66.421 49.149,51.384 43.967,46.203 43.967,42.723 42.85,41.605 42.85,34.252 v3(41.626,33.028)
  BOTTOM w0.127: CN5.5@4.127,81.915 4.826,81.915 5.461,81.28 5.461,78.74 7.62,76.581 v2(7.874,76.581) ; U14.R14@41.249,32.651 v3(41.626,33.028)
PB15: CN5.4 U14.R15 | length 88
  TOP w0.127: v2(8.001,77.216) 9.652,75.565 19.304,75.565 22.479,78.74 37.465,78.74 49.53,66.675 49.53,51.13 44.425,46.025 44.425,39.141 43.51,38.227 43.51,34.112 v3(42.426,33.028)
  BOTTOM w0.127: CN5.4@7.556,79.375 7.556,77.66 v2(8.001,77.216) ; U14.R15@42.049,32.651 v3(42.426,33.028)
PC0: TP2.1 U11.K8 U14.M2 | length 58.4
  TOP w0.127: v2(20.472,41.961) 20.371,42.062 20.371,48.108 20.828,48.565 20.828,54.661 20.955,54.788 23.165,54.788 23.292,54.915 23.292,55.352 23.165,55.479 20.98,55.479 20.853,55.606 20.853,55.86 20.98,55.987 23.165,55.987 23.292,56.114 23.292,58.039 23.419,58.166 28.042,58.166 28.702,58.826 33.794,58.826 v3(34.218,58.403)
  L4_SIG w0.102: v2(20.472,41.961) 20.472,42.393 20.599,42.52 22.809,42.52 22.936,42.393 22.936,41.529 23.063,41.402 23.749,41.402 23.876,41.275 23.876,39.497 23.749,39.37 23.495,39.37 23.368,39.243 23.368,37.058 23.61,36.817 24.523,36.817 24.611,36.728 24.613,36.728 25.527,35.814 25.527,35.052 29.591,30.988 v3(29.591,30.251)
  BOTTOM w0.127: TP2.1@19.939,43.18 19.939,42.494 v2(20.472,41.961) ; v3(29.591,30.251) 29.988,30.648 31.252,30.648 U14.M2@31.649,30.251 ; v3(34.218,58.403) U11.K8@34.595,58.026
PC1: CN12.14 U14.M3 | length 51.1
  TOP w0.102: 29.87,29.769 30.886,29.769 31.471,30.353 32.512,30.353 32.766,30.607 32.887,30.607 v3(32.903,30.623)
  TOP w0.127: v2(25.15,30.29) 25.582,29.857 29.782,29.857 29.87,29.769
  L4_SIG w0.102: v2(25.15,30.29) 26.238,29.201 26.238,28.854 27.127,27.965 27.127,21.387 27.686,20.828 28.999,20.828 30.066,19.761 34.493,19.761 36.525,17.729 41.326,17.729 43.942,15.113 43.942,11.557 v2(43.18,10.795)
  BOTTOM w0.127: U14.M3@32.449,30.251 32.531,30.251 v3(32.903,30.623) ; v2(43.18,10.795) 43.37,10.605 ; 43.37,10.604 43.815,10.16 43.815,5.461 44.958,4.318 CN12.14@44.958,3.113
PC2: CN8.2 U14.M4 | length 105.9
  TOP w0.102: 29.87,29.21 31.564,29.21 31.826,29.473 32.219,29.473 32.592,29.845 v3(32.872,29.845)
  TOP w0.127: v2(7.899,61.519) 8.357,61.062 8.357,57.607 7.747,56.998 7.747,54.686 11.125,51.308 11.125,33.706 12.954,31.877 15.189,31.877 15.875,32.563 18.11,32.563 18.796,31.877 21.314,31.877 24.235,28.956 26.797,28.956 27.051,29.21 29.87,29.21
  L4_SIG w0.102: v2(7.899,61.519) 7.899,61.874 13.462,67.437 34.818,67.437 35.707,66.548 42.799,66.548 47.879,61.468 v2(52.387,61.468)
  BOTTOM w0.127: v3(32.872,29.845) 32.872,29.874 U14.M4@33.249,30.251 ; CN8.2@52.387,60.071 v2(52.387,61.468)
PC3: CN8.3 U14.L4 | length 108
  TOP w0.102: 29.87,28.956 31.467,28.956 31.75,28.673 32.219,28.673 32.249,28.702 32.258,28.702 32.634,29.078 v3(32.867,29.078)
  TOP w0.127: v2(7.899,60.833) 7.747,60.681 7.747,57.633 7.366,57.252 7.366,54.432 10.795,51.003 10.795,33.528 12.827,31.496 21.336,31.496 24.13,28.702 27.051,28.702 27.305,28.956 29.87,28.956
  L4_SIG w0.102: v2(7.899,60.833) 8.026,60.96 8.636,60.96 8.89,61.214 8.89,62.357 10.287,63.754 19.939,63.754 22.022,65.837 42.494,65.837 48.133,60.198 50.673,60.198 53.34,57.531 v2(53.975,57.531)
  BOTTOM w0.127: v3(32.867,29.078) 32.876,29.078 U14.L4@33.249,29.451 ; v2(53.975,57.531) CN8.3@55.816,57.531
PC4: CN8.4 U14.N5 | length 118.8
  TOP w0.102: 29.87,26.594 30.074,26.797 33.655,26.797 34.036,27.178 34.036,29.972 33.782,30.226 33.401,30.226 33.274,30.353 33.274,30.785 33.672,31.183 v3(33.672,31.428)
  TOP w0.127: v2(6.96,60.909) 6.604,60.554 6.604,36.703 12.751,30.556 17.196,30.556 18.237,29.515 20.269,29.515 21.336,28.448 22.149,28.448 24.816,25.781 28.956,25.781 29.718,26.543 29.82,26.543 29.87,26.594
  L4_SIG w0.102: v2(6.96,60.909) 7.62,60.249 8.56,60.249 9.271,60.96 9.271,62.23 10.414,63.373 20.066,63.373 22.225,65.532 42.291,65.532 52.832,54.991 v2(54.102,54.991)
  BOTTOM w0.127: v3(33.672,31.428) U14.N5@34.049,31.051 ; CN8.4@52.387,54.991 v2(54.102,54.991)
PC5: SB10.1 U14.P5 | length 73.9
  TOP w0.127: v2(17.145,56.134) 17.145,38.354 17.399,38.1 18.542,38.1 19.38,37.262 21.412,37.262 22.606,36.068 24.435,36.068 26.086,34.417 33.11,34.417 33.672,33.856 v3(33.672,32.228)
  L4_SIG w0.102: v2(17.145,56.134) 23.495,56.134 26.035,58.674 26.035,60.37 28.784,63.119 42.164,63.119 v2(45.085,60.198)
  BOTTOM w0.127: v3(33.672,32.228) U14.P5@34.049,31.851 ; v2(45.085,60.198) 46.736,60.198 46.863,60.071 46.99,59.944 SB10.1@47.371,59.563
PC6: CN12.6 U14.H15 | length 36.4
  L4_SIG w0.102: v2(34.823,5.563) 35.808,4.578 40.519,4.578 46.609,10.668 46.609,12.954 46.228,13.335 46.228,19.304 45.085,20.447 45.085,25.379 44.404,26.06 v3(44.399,26.06)
  BOTTOM w0.127: CN12.6@34.798,3.113 34.798,5.537 v2(34.823,5.563) ; U14.H15@42.049,27.051 42.405,26.695 43.942,26.695 44.348,26.289 44.348,26.116 44.399,26.065 v3(44.399,26.06)
PC7: CN12.8 U14.G15 | length 32.2
  L4_SIG w0.102: v2(37.338,5.588) 38.1,4.826 40.259,4.826 46.101,10.668 46.101,12.37 45.72,12.751 45.72,18.796 44.676,19.84 44.676,25.239 v3(43.853,26.061)
  BOTTOM w0.127: CN12.8@37.338,3.113 v2(37.338,5.588) ; U14.G15@42.049,26.251 43.663,26.251 v3(43.853,26.061)
PC8: CN9.7 R114.2 U14.G14 | length 73.5
  L4_SIG w0.102: v2(12.929,38.961) 12.573,38.606 12.573,35.839 14.249,34.163 14.249,17.805 16.205,15.85 18.628,15.85 19.216,15.261 26.92,15.261 28.778,17.12 41.173,17.12 43.002,15.291 43.002,14.783 v2(43.053,14.732) ; v3(44.221,24.982) 44.221,19.583 v2(44.831,18.974)
  BOTTOM w0.127: v2(12.929,38.961) 13.284,39.317 CN9.7@15.071,39.317 16.838,39.317 R114.2@17.272,39.751 ; U14.G14@41.249,26.251 41.643,25.857 43.221,25.857 43.69,25.388 43.979,25.388 44.221,25.146 v3(44.221,24.982) ; v2(43.053,14.732) 43.434,15.113 43.434,17.704 44.704,18.974 v2(44.831,18.974)
PC9: R135.1 U14.F14 | length 9.6
  L4_SIG w0.102: v2(42.291,19.583) 42.291,20.98 41.478,21.793 41.478,23.216 42.164,23.901 42.164,24.765 v3(42.52,25.121)
  BOTTOM w0.127: U14.F14@41.249,25.451 41.651,25.049 42.448,25.049 v3(42.52,25.121) ; v2(42.291,19.583) 42.418,19.456 R135.1@42.418,17.78
PC10: CN9.1 R120.2 U14.B14 | length 61
  L4_SIG w0.102: v2(13.462,32.639) 13.665,32.436 13.665,17.551 15.824,15.392 18.438,15.392 19.048,14.783 27.21,14.783 29.014,16.586 40.818,16.586 41.783,15.621 v2(41.783,14.351)
  BOTTOM w0.127: v2(13.462,32.639) 13.54,32.717 CN9.1@15.071,32.717 15.572,32.717 16.51,33.655 16.51,34.798 R120.2@17.272,35.56 ; U14.B14@41.249,22.251 40.843,21.845 40.843,20.752 41.656,19.939 41.656,14.478 v2(41.783,14.351)
PC11: CN9.2 R116.2 U14.B13 | length 58.9
  L4_SIG w0.102: v2(13.335,34.036) 12.954,33.655 12.954,32.461 13.386,32.029 13.386,17.45 15.672,15.164 18.344,15.164 18.953,14.554 27.305,14.554 29.108,16.358 40.31,16.358 v2(40.615,16.053)
  BOTTOM w0.127: v2(13.335,34.036) 13.335,34.071 13.589,33.817 CN9.2@15.071,33.817 15.529,33.817 16.129,34.417 16.129,34.925 16.637,35.433 16.637,36.195 R116.2@17.272,36.83 ; U14.B13@40.449,22.251 40.048,21.85 40.048,20.455 40.615,19.888 v2(40.615,16.053)
PC12: CN9.5 U14.A12 | length 58.8
  L4_SIG w0.102: v2(12.065,34.798) 12.548,34.315 12.548,32.487 13.132,31.902 13.132,17.348 15.545,14.935 18.198,14.935 18.808,14.326 27.476,14.326 29.279,16.129 39.853,16.129 v2(40.589,15.392)
  BOTTOM w0.127: v2(12.065,34.798) 12.065,36.101 13.081,37.117 CN9.5@15.071,37.117 ; U14.A12@39.649,21.451 39.649,20.168 40.005,19.812 40.005,15.977 v2(40.589,15.392)
PC13: CN12.13 U14.D1 | length 29.7
  L4_SIG w0.102: v3(29.185,19.964) 29.743,19.406 34.354,19.406 36.361,17.399 41.275,17.399 43.586,15.088 43.586,12.167 v2(43.231,11.811)
  BOTTOM w0.127: v3(29.185,19.964) 29.337,20.117 29.337,23.368 30.099,24.13 30.57,24.13 U14.D1@30.849,23.851 ; v2(43.231,11.811) 44.958,10.084 CN12.13@44.958,8.063
PC14: R132.2 U14.E1 | length 9.7
  BOTTOM w0.203: R132.2@24.13,20.066 25.019,20.955 28.321,20.955 28.956,21.59 28.956,23.495 30.112,24.651 U14.E1@30.849,24.651
PC15: R133.2 U14.F1 | length 9.1
  BOTTOM w0.203: R133.2@24.13,21.59 24.765,22.225 28.321,22.225 28.575,22.479 28.575,23.749 30.277,25.451 U14.F1@30.849,25.451
PD2: CN9.3 R115.2 U14.D12 | length 64.1
  L4_SIG w0.102: v2(12.04,34.036) 12.04,32.487 12.878,31.648 12.878,17.12 15.291,14.707 18.103,14.707 18.713,14.097 30.734,14.097 32.258,15.621 v2(37.363,15.621) ; v2(37.363,18.758) 36.449,19.672 36.449,23.927 37.16,24.638 38.837,24.638 v3(39.243,24.232)
  BOTTOM w0.102: v3(39.243,24.232) 39.623,23.851 U14.D12@39.649,23.851
  BOTTOM w0.127: v2(12.04,34.036) 12.921,34.917 CN9.3@15.071,34.917 15.486,34.917 16.256,35.687 16.256,37.338 17.145,38.227 R115.2@17.272,38.227 ; v2(37.363,15.621) v2(37.363,18.758)
PD3: CN5.6 SB5.2 U14.C11 | length 106.7
  TOP w0.102: 36.601,20.472 36.957,20.828 36.957,22.157 37.211,22.411 37.211,22.733 37.592,23.114 38.1,23.114 38.445,22.769 v3(38.445,22.702)
  TOP w0.127: v2(34.493,18.542) 34.671,18.542 36.601,20.472
  L4_SIG w0.102: v2(8.407,82.118) 7.95,82.118 4.191,78.359 4.191,55.118 6.299,53.01 6.299,44.196 9.906,40.589 12.04,40.589 13.564,39.065 13.564,35.23 14.503,34.29 14.503,18.034 16.459,16.078 18.723,16.078 19.307,15.494 26.772,15.494 28.804,17.526 33.477,17.526 v2(34.493,18.542)
  BOTTOM w0.127: CN5.6@7.556,84.455 7.556,82.969 v2(8.407,82.118) 9.119,81.407 SB5.2@10.668,81.407 ; v3(38.445,22.702) 38.794,23.051 U14.C11@38.849,23.051
PD4: R3.1 U14.D11 | length 166
  TOP w0.127: R3.1@21.971,120.142 20.93,119.101 18.136,119.101 13.843,114.808 13.843,110.795 14.783,109.856 14.783,100.533 11.456,97.206 5.258,97.206 1.6,93.548 1.6,17.831 9.906,9.525 18.847,9.525 21.387,12.065 26.797,12.065 27.94,13.208 29.413,13.208 33.439,17.234 34.43,17.234 37.77,20.574 38.481,20.574 38.862,20.955 38.862,22.098 38.989,22.225 39.37,22.225 39.624,22.479 39.624,22.733 39.606,22.751 39.606,22.769 39.226,23.149 v3(39.226,23.474)
  BOTTOM w0.102: U14.D11@38.849,23.851 v3(39.226,23.474)
PD5: R4.1 U14.C10 | length 166.4
  TOP w0.127: R4.1@26.67,120.142 26.67,119.072 26.292,118.694 18.567,118.694 15.189,115.316 15.189,100.203 11.786,96.799 5.537,96.799 1.93,93.193 1.93,18.009 10.033,9.906 18.796,9.906 21.209,12.319 26.543,12.319 27.686,13.462 29.21,13.462 33.376,17.628 34.239,17.628 37.258,20.646 37.258,22.145 37.665,22.552 v3(37.665,22.681)
  BOTTOM w0.127: v3(37.665,22.681) 38.035,23.051 U14.C10@38.049,23.051
PD6: SB17.2 SB18.2 U2.4 U14.B11 | length 191.3
  TOP w0.127: SB17.2@8.382,124.841 8.382,120.396 13.411,115.367 13.411,110.616 14.402,109.626 14.402,100.763 11.302,97.663 5.105,97.663 1.27,93.828 1.27,17.628 9.754,9.144 20.701,9.144 23.749,6.096 25.4,6.096 26.848,7.544 v2(26.924,7.544) 27.127,7.544 27.305,7.366 27.305,6.604 27.896,6.013 U2.4@28.154,6.013 ; v2(44.856,11.659) 45.339,11.176 SB18.2@45.339,6.604
  L4_SIG w0.102: v2(26.924,7.544) 27.432,8.052 32.842,8.052 34.442,9.652 43.618,9.652 44.856,10.89 v2(44.856,11.659) 44.856,16.357 39.929,21.285 39.929,21.742 39.238,22.434 v3(39.238,22.617)
  BOTTOM w0.127: U14.B11@38.849,22.251 38.872,22.251 v3(39.238,22.617)
PD7: U14.A11
PD13: R87.2 U14.M11 | length 16.5
  TOP w0.102: v3(39.226,30.628) 39.226,30.887 39.62,31.281 39.62,31.619 39.874,31.873 41.067,31.873 41.834,32.639
  TOP w0.127: 41.834,32.639 42.585,32.639 45.74,35.794 45.74,37.993 v2(48.387,40.64)
  BOTTOM w0.127: U14.M11@38.849,30.251 v3(39.226,30.628) ; R87.2@47.498,40.894 48.133,40.894 v2(48.387,40.64)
